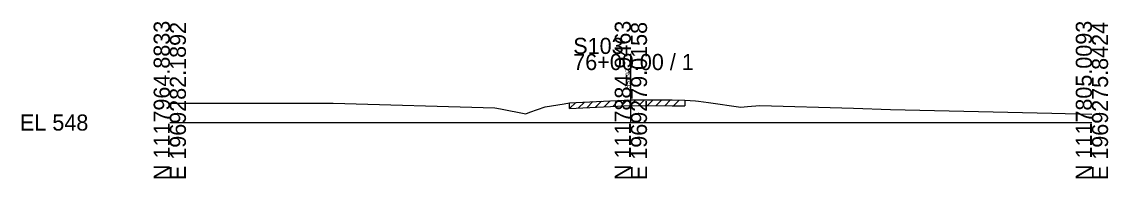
# Model space of a CAD drawing. Extents: x -26 to 163, y -10 to 24018.
# Drawn here: x -25.7 to 162.8, y 23990.3 to 24017.5 of the extents above; entities that cross this region are included whole.
import ezdxf

# ---------------------------------------------------------------- set-up
doc = ezdxf.new("R2010")
doc.units = 0
for name, color, linetype in [('RD_GPK_XS_Cell', 7, 'Continuous'), ('RD_XS_ExGround', 7, 'Continuous'), ('RD_XS_ExPaveRet', 7, 'Continuous'), ('RD_XS_TX_Elev_EX', 7, 'Continuous')]:
    doc.layers.add(name, color=color, linetype=linetype)

msp = doc.modelspace()

# ---------------------------------------------------------------- linework, layer by layer
at = {"layer": 'RD_GPK_XS_Cell'}
for p, q in [((80, 24000), (80, 24011.92)), ((0, 24000), (80, 24000)), ((80, 24000), (160, 24000))]:
    msp.add_line(p, q, dxfattribs=at)
at = {"layer": 'RD_XS_ExGround'}
msp.add_lwpolyline([(0, 24003.37), (27.98, 24003.36), (28.34, 24003.35), (56.38, 24002.57), (57.39, 24002.37), (61.75, 24001.53), (62.48, 24001.79), (65.16, 24002.71), (68.41, 24003.27), (69.38, 24003.43), (71.69, 24003.54), (80.03, 24003.97), (87.17, 24003.92), (89.36, 24003.9), (91.21, 24003.76), (91.76, 24003.72), (93.5, 24003.48), (99.11, 24002.68), (100.23, 24002.78), (102.39, 24002.97), (118.65, 24002.48), (125.05, 24002.28), (153.05, 24001.65), (160, 24001.46)], dxfattribs=at)
at = {"layer": 'RD_XS_ExPaveRet'}
for p, q in [((69.38, 24002.43), (70.43, 24003.48)), ((69.38, 24002.43), (69.38, 24003.43)), ((69.38, 24002.43), (71.69, 24002.54)), ((70.88, 24002.5), (71.93, 24003.55)), ((71.69, 24002.54), (80.03, 24002.97)), ((72.38, 24002.57), (73.43, 24003.63)), ((73.88, 24002.65), (74.93, 24003.71)), ((75.38, 24002.73), (76.43, 24003.79)), ((76.88, 24002.81), (77.93, 24003.86)), ((78.38, 24002.89), (79.43, 24003.94)), ((79.88, 24002.97), (80.88, 24003.97)), ((80.03, 24002.97), (87.17, 24002.92)), ((81.38, 24002.96), (82.37, 24003.96)), ((82.88, 24002.95), (83.87, 24003.95)), ((84.38, 24002.94), (85.37, 24003.94)), ((85.88, 24002.93), (86.87, 24003.93)), ((87.17, 24002.92), (89.36, 24002.9)), ((87.38, 24002.92), (88.37, 24003.91)), ((89.36, 24003.9), (89.36, 24002.9))]:
    msp.add_line(p, q, dxfattribs=at)

# ---------------------------------------------------------------- texts
at = {"layer": 'RD_GPK_XS_Cell'}
for s, p in [('N 1117964.8833', (0, 23990)), ('E 1969282.1892', (2.8, 23990)), ('N 1117884.9463', (80, 23990)), ('E 1969279.0158', (82.8, 23990)), ('N 1117805.0093', (160, 23990)), ('E 1969275.8424', (162.8, 23990))]:
    msp.add_text(s, height=2.8, rotation=90, dxfattribs=at).set_placement(p)
for s, p in [('S103', (70, 24011.92)), ('76+00.00 / 1', (70, 24009.12)), ('EL 548', (-26, 23998.6))]:
    msp.add_text(s, height=2.8, dxfattribs=at).set_placement(p)
at = {"layer": 'RD_XS_TX_Elev_EX'}
msp.add_text('551.97', height=0.8, rotation=90, dxfattribs=at).set_placement((79.9, 24005.97))

doc.saveas('drawing.dxf')
